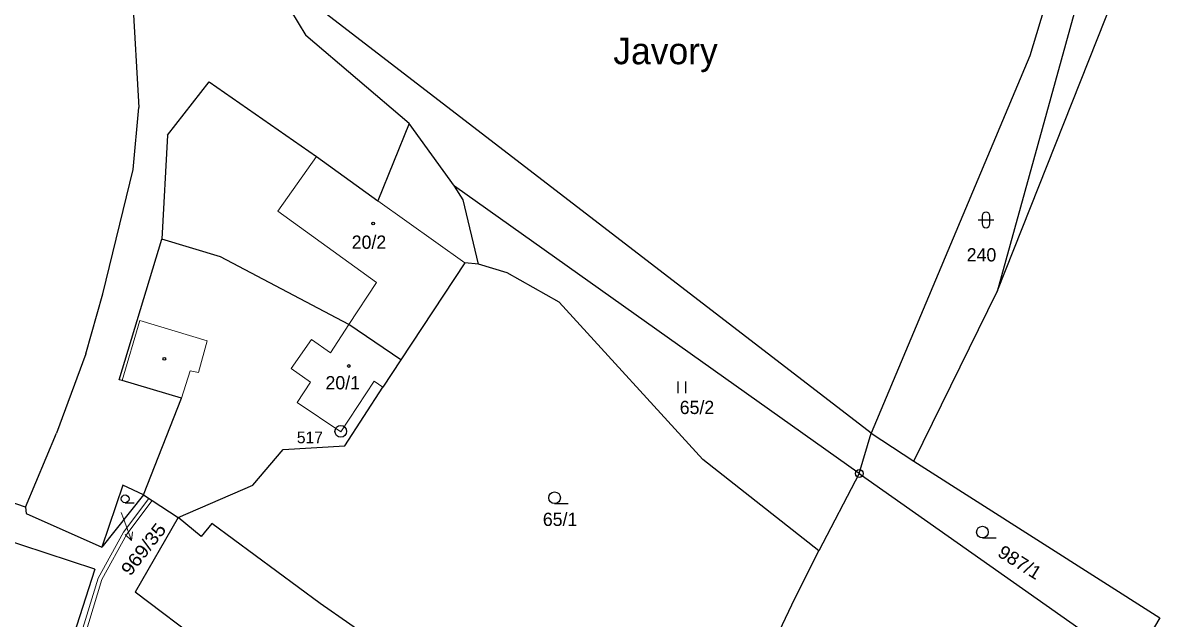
# Model space of a CAD drawing. Extents: x -754970 to -752637, y -970569 to -968179.
# Drawn here: x -753121.7 to -752973.4, y -969382.5 to -969306.2 of the extents above; entities that cross this region are included whole.
import ezdxf
from ezdxf.enums import TextEntityAlignment as Align

# ---------------------------------------------------------------- set-up
doc = ezdxf.new("R2010")
doc.units = 0
doc.header["$LTSCALE"] = 0.68
for name, color, linetype, lineweight in [('1', 7, 'Continuous', 25), ('13', 7, 'Continuous', 13), ('3', 7, 'Continuous', 25), ('4', 7, 'Continuous', 13), ('5', 7, 'Continuous', 25), ('7', 7, 'Continuous', 13), ('8', 7, 'Continuous', 25)]:
    doc.layers.add(name, color=color, linetype=linetype, lineweight=lineweight)
doc.layers.add('2', color=7, linetype='Continuous')

msp = doc.modelspace()

# ---------------------------------------------------------------- linework, layer by layer
at = {"layer": '1'}
for p, q in [((-752980.16, -969280.31), (-752996.83, -969340.57)), ((-752983.37, -969279.86), (-752992.66, -969310.37)), ((-752996.83, -969340.57), (-752973.43, -969281.59)), ((-753097.69, -969287.26), (-753085.49, -969307.78)), ((-753108.2, -969293.86), (-753106.86, -969317.01)), ((-753013.01, -969358.68), (-753083.39, -969304.6)), ((-753072.21, -969319.02), (-753085.49, -969307.78)), ((-752992.66, -969310.37), (-753013.01, -969358.68)), ((-753103.21, -969320.53), (-753097.86, -969313.71)), ((-753097.86, -969313.71), (-753084.1, -969323.28)), ((-753107.6, -969324.95), (-753106.86, -969317.01)), ((-753072.21, -969319.02), (-753076.25, -969328.94)), ((-753066.41, -969327.08), (-753072.21, -969319.02)), ((-753103.21, -969320.53), (-753103.92, -969333.85)), ((-753084.1, -969323.28), (-753076.25, -969328.94)), ((-753111.48, -969340.84), (-753107.6, -969324.95)), ((-753065.32, -969328.83), (-753066.41, -969327.08)), ((-753014.52, -969363.86), (-753066.41, -969327.08)), ((-753063.33, -969337.04), (-753065.32, -969328.83)), ((-753109.41, -969351.88), (-753103.92, -969333.85)), ((-753096.39, -969336.13), (-753103.92, -969333.85)), ((-753079.97, -969344.76), (-753096.39, -969336.13)), ((-753065.07, -969336.88), (-753073.28, -969349.29)), ((-753063.33, -969337.04), (-753065.07, -969336.88)), ((-753059.65, -969338.18), (-753063.33, -969337.04)), ((-753052.99, -969341.92), (-753059.65, -969338.18)), ((-753113.67, -969348.53), (-753111.48, -969340.84)), ((-753034.57, -969362.08), (-753052.99, -969341.92)), ((-753007.55, -969362.28), (-752996.83, -969340.57)), ((-753073.28, -969349.29), (-753079.97, -969344.76)), ((-753113.67, -969348.53), (-753117.44, -969358.71)), ((-753073.28, -969349.29), (-753075.61, -969352.81)), ((-753109.02, -969351.97), (-753109.41, -969351.88)), ((-753101.41, -969354.2), (-753109.02, -969351.97)), ((-753080.49, -969360.31), (-753075.61, -969352.81)), ((-753106.3, -969366.58), (-753101.41, -969354.2)), ((-753121.39, -969368.19), (-753147.49, -969359.23)), ((-753121.39, -969368.19), (-753117.44, -969358.71)), ((-753014.52, -969363.86), (-753013.01, -969358.68)), ((-753013.01, -969358.68), (-753007.55, -969362.28)), ((-753092.25, -969365.35), (-753088.36, -969360.78)), ((-753088.36, -969360.78), (-753080.49, -969360.31)), ((-753019.73, -969373.76), (-753034.57, -969362.08)), ((-753007.55, -969362.28), (-752975.98, -969382.36)), ((-753014.52, -969363.86), (-753019.73, -969373.76)), ((-753014.52, -969363.86), (-752979.63, -969388.38)), ((-753108.94, -969365.37), (-753111.63, -969373.31)), ((-753106.3, -969366.58), (-753108.94, -969365.37)), ((-753101.82, -969369.48), (-753092.25, -969365.35)), ((-753112.53, -969376.1), (-753141.52, -969366.63)), ((-753106.3, -969366.58), (-753111.63, -969373.31)), ((-753106.3, -969366.58), (-753101.82, -969369.48)), ((-753121.39, -969368.19), (-753121.32, -969368.99)), ((-753121.32, -969368.99), (-753111.63, -969373.31)), ((-753101.82, -969369.48), (-753107.35, -969379.07)), ((-753098.88, -969371.93), (-753101.82, -969369.48)), ((-753097.52, -969370.25), (-753098.88, -969371.93)), ((-753083.63, -969380.5), (-753097.52, -969370.25)), ((-753022.73, -969379.76), (-753019.73, -969373.76)), ((-753112.53, -969376.1), (-753116.59, -969388.67)), ((-753091.37, -969391.06), (-753107.35, -969379.07)), ((-753027.39, -969389.48), (-753022.73, -969379.76)), ((-753062.94, -969394.9), (-753083.63, -969380.5)), ((-752975.98, -969382.36), (-752979.63, -969388.38))]:
    msp.add_line(p, q, dxfattribs=at)
at = {"layer": '13'}
msp.add_lwpolyline([(-753113.86, -969384.78), (-753111.61, -969377.45), (-753108.43, -969371.63), (-753105.17, -969367.31), (-753105.59, -969367.04), (-753108.85, -969371.36), (-753112.08, -969377.25), (-753114.34, -969384.65)], dxfattribs=at)
at = {"layer": '3'}
for p, q in [((-752999.281, -969331.381), (-752997.279, -969331.381)), ((-752998.781, -969330.881), (-752998.781, -969331.882)), ((-752997.779, -969331.882), (-752997.779, -969330.881)), ((-753037.761, -969353.56), (-753037.761, -969352.06)), ((-753036.76, -969353.56), (-753036.76, -969352.06)), ((-753108.635, -969367.61), (-753107.463, -969367.61)), ((-753053.583, -969367.72), (-753051.833, -969367.72)), ((-752998.743, -969372.11), (-752996.993, -969372.11))]:
    msp.add_line(p, q, dxfattribs=at)
for centre, radius in [((-753108.6352, -969367.1074), 0.5025), ((-753053.5829, -969366.9698), 0.75), ((-752998.7429, -969371.3598), 0.75)]:
    msp.add_circle(centre, radius, dxfattribs=at)
for centre, start, end in [((-752998.28, -969330.8809), 0, 180), ((-752998.28, -969331.8809), 180, 359.98789)]:
    msp.add_arc(centre, 0.5, start, end, dxfattribs=at)
at = {"layer": '4'}
for p, q in [((-753089.08, -969330.25), (-753084.1, -969323.28)), ((-753065.07, -969336.88), (-753076.25, -969328.94)), ((-753076.42, -969339.39), (-753089.08, -969330.25)), ((-753076.42, -969339.39), (-753079.97, -969344.76)), ((-753106.75, -969344.25), (-753109.02, -969351.97)), ((-753106.75, -969344.25), (-753098.13, -969346.86)), ((-753082.33, -969348.4), (-753079.97, -969344.76)), ((-753098.13, -969346.86), (-753099.23, -969350.92)), ((-753087.37, -969350.43), (-753084.73, -969346.7)), ((-753084.73, -969346.7), (-753082.33, -969348.4)), ((-753100.29, -969350.71), (-753101.41, -969354.2)), ((-753099.23, -969350.92), (-753100.29, -969350.71)), ((-753084.88, -969352.15), (-753087.37, -969350.43)), ((-753086.59, -969354.77), (-753084.88, -969352.15)), ((-753081, -969358.52), (-753076.72, -969352.05)), ((-753076.72, -969352.05), (-753075.61, -969352.81)), ((-753081, -969358.52), (-753086.59, -969354.77))]:
    msp.add_line(p, q, dxfattribs=at)
at = {"layer": '5'}
for centre in [(-753076.8368, -969331.8492), (-753103.6068, -969349.1592), (-753079.9468, -969350.0892)]:
    msp.add_circle(centre, 0.175, dxfattribs=at)
at = {"layer": '7'}
msp.add_line((-753107.824, -969372.44), (-753107.696, -969371.328), dxfattribs=at)
msp.add_lwpolyline([(-753109.13, -969368.87), (-753108.85, -969369.62), (-753107.824, -969372.44), (-753108.637, -969371.67)], dxfattribs=at)
at = {"layer": '8'}
for centre, radius in [((-753080.99, -969358.4598), 0.75), ((-753080.99, -969358.4598), 0.03), ((-753014.52, -969363.8599), 0.5), ((-753014.52, -969363.8599), 0.0303)]:
    msp.add_circle(centre, radius, dxfattribs=at)

# ---------------------------------------------------------------- texts
at = {"layer": '2'}
for s, p in [('20/2', (-753077.379, -969335.085)), ('240', (-752998.859, -969336.705)), ('20/1', (-753080.739, -969353.085)), ('65/2', (-753035.329, -969356.245)), ('65/1', (-753052.879, -969370.575))]:
    msp.add_text(s, height=1.7, dxfattribs=at).set_placement(p, align=Align.CENTER)
at = {"layer": '2', "width": 1.1}
msp.add_text('969/35', height=1.7, rotation=52, dxfattribs=at).set_placement((-753107.968, -969377.089))
at = {"layer": '2', "width": 1.05}
msp.add_text('987/1', height=1.7, rotation=328, dxfattribs=at).set_placement((-752994.3959, -969375.9529), align=Align.CENTER)
at = {"layer": '7'}
msp.add_text('Javory', height=3.4, dxfattribs=at).set_placement((-753046.06, -969311.45))
at = {"layer": '8'}
msp.add_text('517', height=1.5, dxfattribs=at).set_placement((-753083.277, -969359.986), align=Align.RIGHT)

doc.saveas('drawing.dxf')
